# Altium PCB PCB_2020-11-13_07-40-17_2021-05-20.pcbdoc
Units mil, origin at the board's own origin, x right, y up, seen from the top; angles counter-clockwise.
Board outline 3315 x 2420 mil, 2 copper layers (Top Layer, Bottom Layer); 15 components, 15 nets, 52 pads, 0 vias.
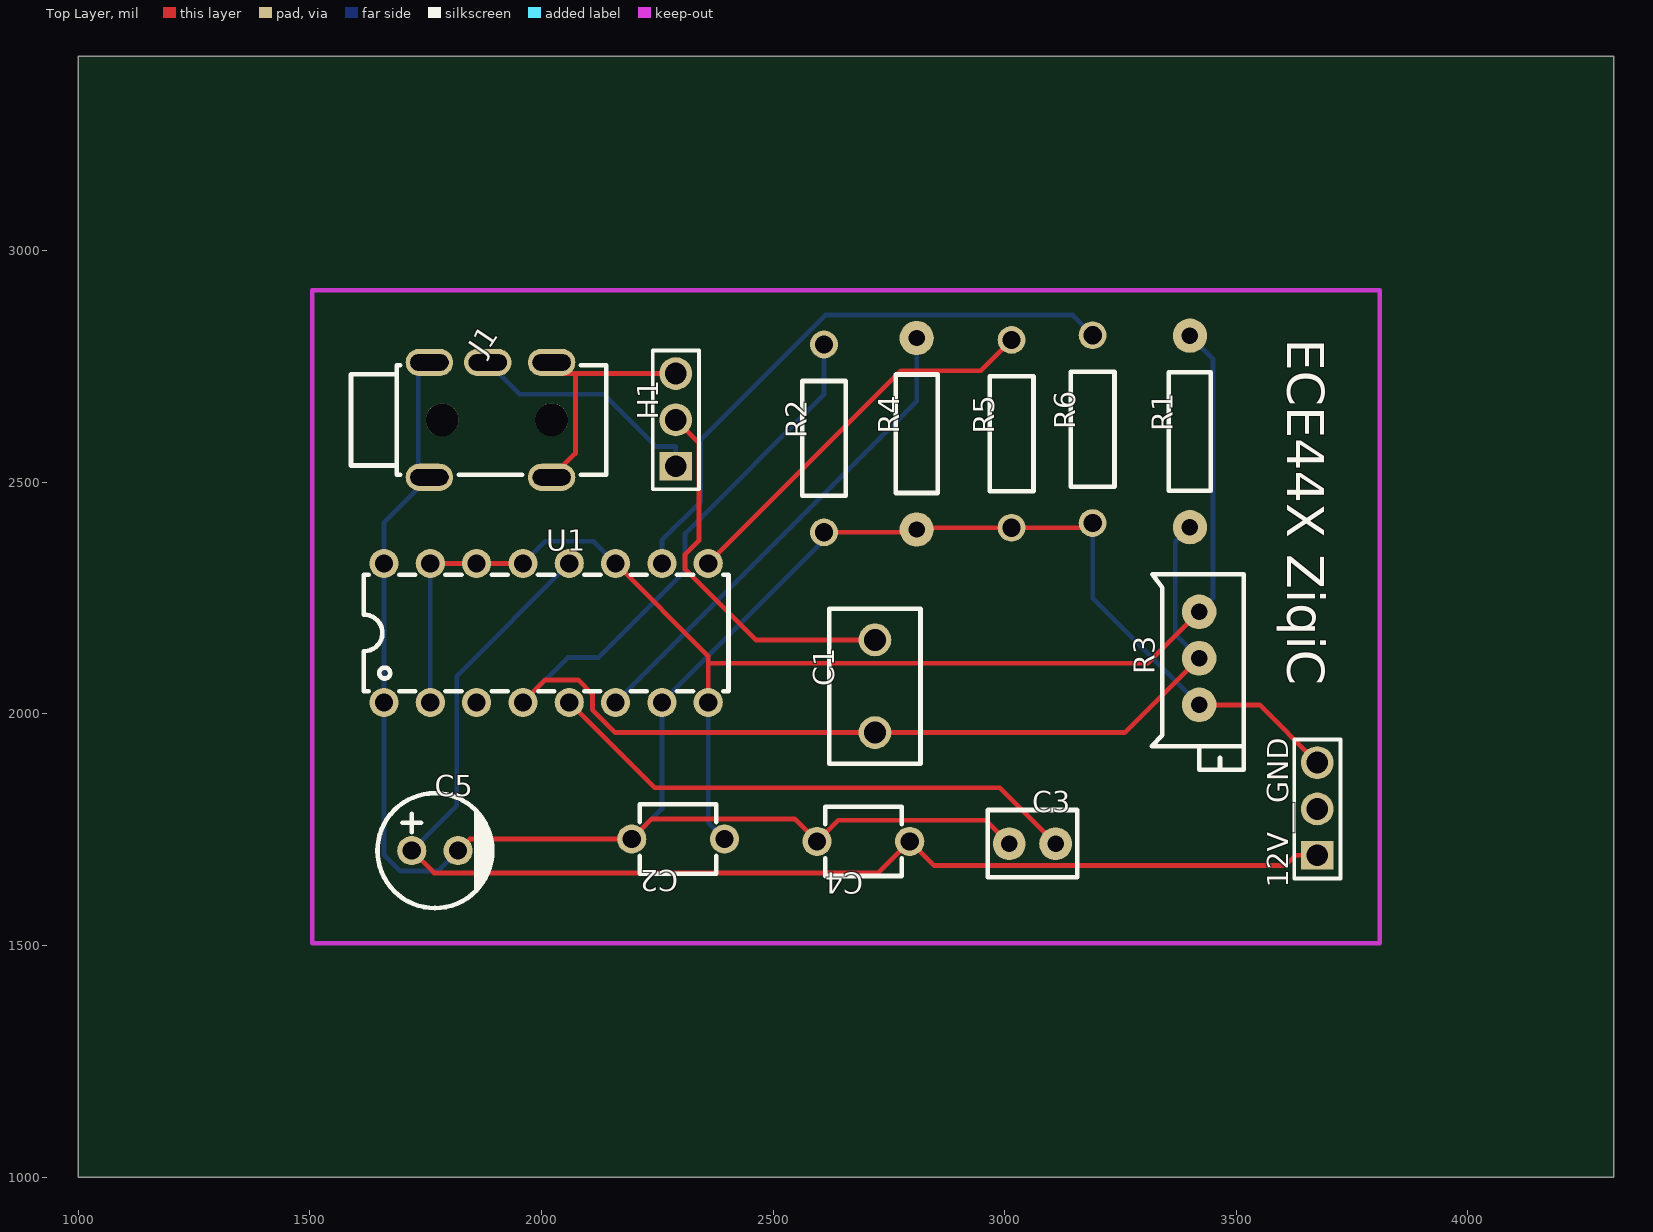
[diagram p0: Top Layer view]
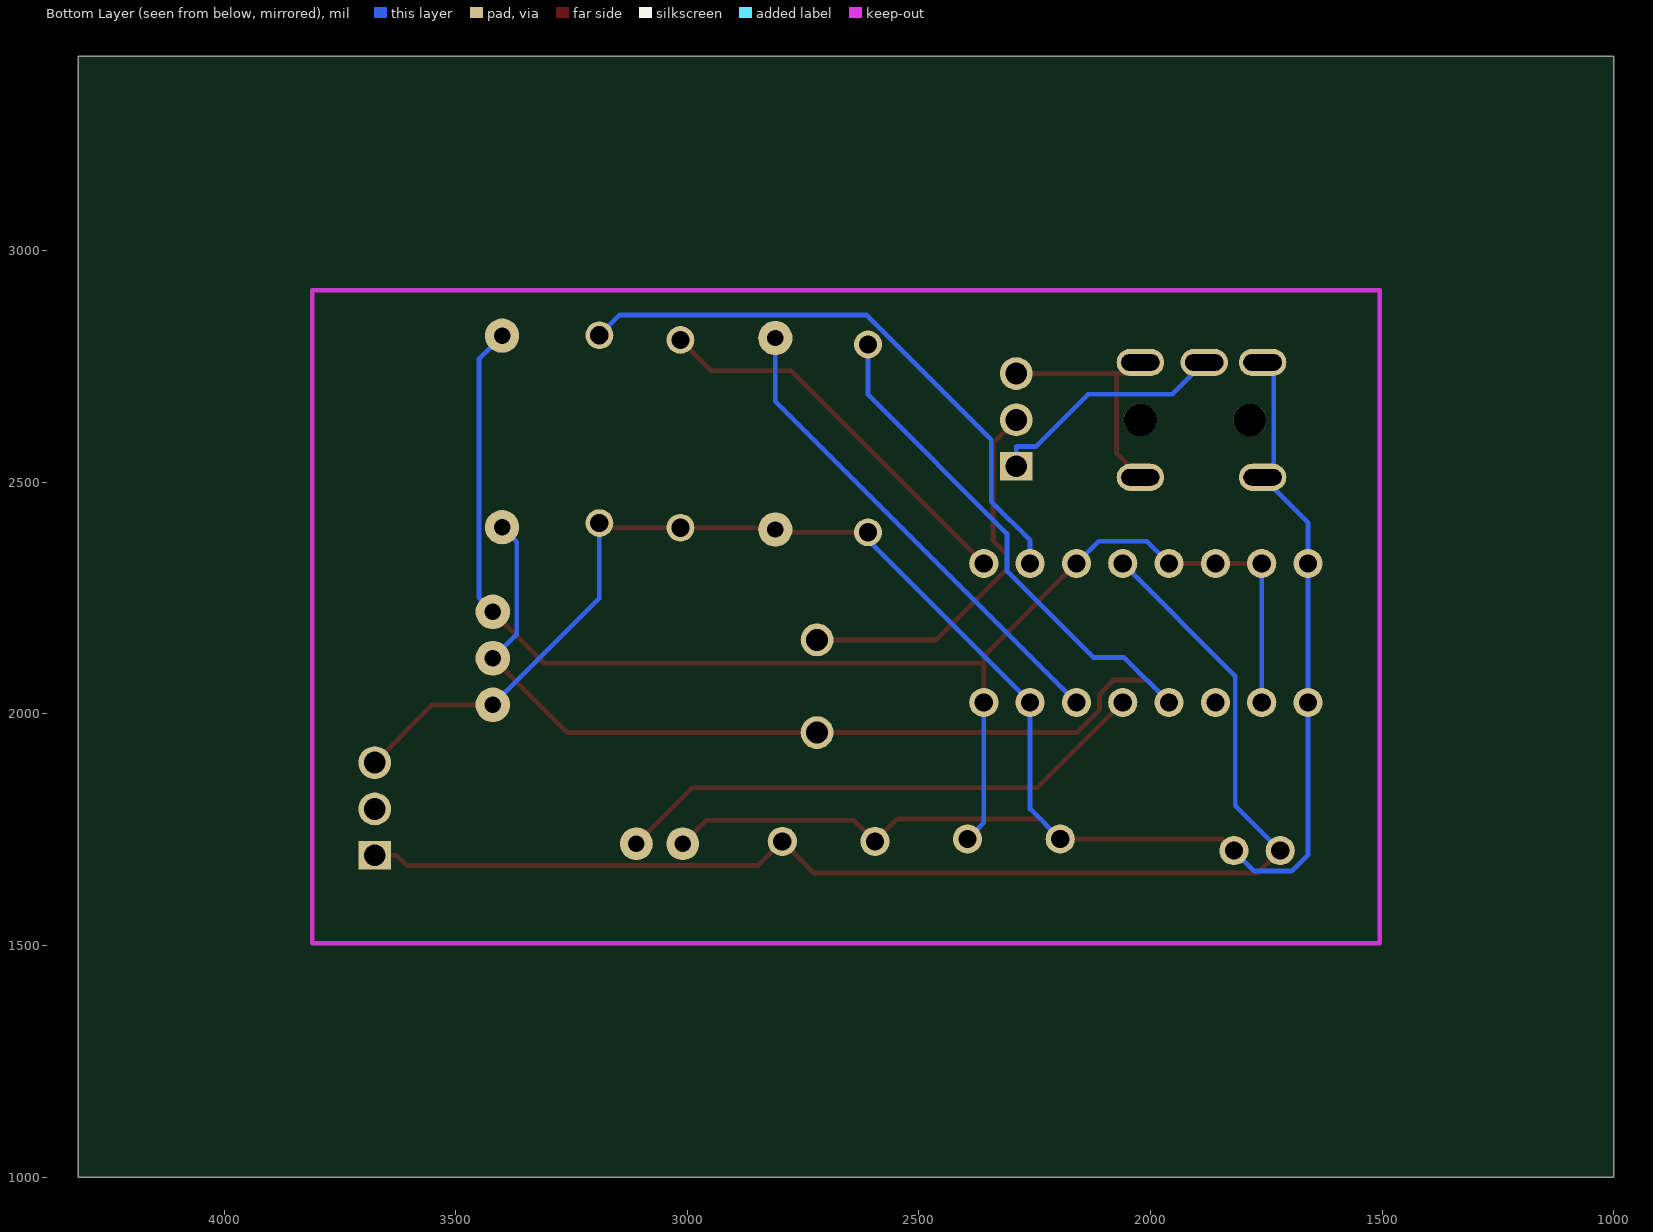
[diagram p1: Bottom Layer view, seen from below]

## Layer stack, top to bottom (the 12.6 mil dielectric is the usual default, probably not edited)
Top Layer: signal copper (thickness not stored)
Dielectric: dielectric 12.6, FR-4, Dk 4.8
Bottom Layer: signal copper (thickness not stored)

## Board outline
4315,1000 1000,1000 1000,3420 4315,3420

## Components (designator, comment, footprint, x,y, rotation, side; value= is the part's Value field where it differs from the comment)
12V__GND "12251103CNG0S115001" HDR-TH_3P-P2.54-V 3675,1795 r90 top
C1 "1uF" CAP-TH_L8.5-W5.0-P5.00-D1.2 2720,2060 r90 top
C2 "100nF" CAP-TH_L4.2-W3.8-P5.08-D0.5 2295,1730 r180 top
C3 "2.2nF" CAP-TH_L4.9-W3.7-P2.54-D0.5 3060,1720 r0 top
C4 "100nF" CAP-TH_L4.2-W3.8-P5.08-D0.5 2695,1725 r180 top
C5 "100uF" CAP-TH_BD6.3-P2.50-D1.0-FD 1770,1705 r0 top
H1 "12251103CNG0S115001" HDR-TH_3P-P2.54-V 2290,2635 r90 top
J1 "PJ313D" AUDIO-TH_PJ313D 1890,2635 r0 top
R1 "7.5K" RES-TH_BD2.3-L6.5-P10.50-D0.5 3400,2610 r90 top
R2 "2.7K" RES-TH_BD2.4-L6.3-P10.30-D0.6 2610,2595 r90 top
R3 "50K" RES-ADJ-TH_3P-L9.5-W4.9-P2.50-L_3296X 3420,2120 r90 top
R4 "7.5K" RES-TH_BD2.3-L6.5-P10.50-D0.5 2810,2605 r90 top
R5 "10K" RES-TH_BD2.4-L6.3-P10.30-D0.6 3015,2605 r90 top
R6 "10K" RES-TH_BD2.4-L6.3-P10.30-D0.6 3190,2615 r90 top
U1 "TL494N" DIP-16_L20.0-W6.4-P2.54-LS7.6-BL 2010,2175 r0 top

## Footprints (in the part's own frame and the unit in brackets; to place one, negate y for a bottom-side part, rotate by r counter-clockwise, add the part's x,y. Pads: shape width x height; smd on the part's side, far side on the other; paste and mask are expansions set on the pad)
AUDIO-TH_PJ313D [mm]
  oval 2.6x1.5 hole 0.9 slot 2.1 at 0 deg: 2(-3.35,-3.15) 2(-3.35,3.15) 3(-0.15,3.15) 4(3.35,-3.15) 4(3.35,3.15)
  round 1.8 hole 1.8 unplated: ""(-2.65,0) ""(3.35,0)
  silkscreen extent -7.65,-3 6.35,3
CAP-TH_BD6.3-P2.50-D1.0-FD [mm]
  round 1.6 hole 1: 1(-1.27,0) 2(1.27,0)
  silkscreen extent -3.15,-3.15 3.17,3.15
CAP-TH_L4.2-W3.8-P5.08-D0.5 [mm]
  round 1.6 hole 1: 1(-2.54,0) 2(2.54,0)
  silkscreen extent -2.1,-1.9 2.1,1.9
CAP-TH_L4.9-W3.7-P2.54-D0.5 [mm]
  round 1.8 hole 0.9: 1(-1.27,0) 2(1.27,0)
  silkscreen extent -2.45,-1.85 2.45,1.85
CAP-TH_L8.5-W5.0-P5.00-D1.2 [mm]
  round 1.8 hole 1.2: 1(-2.54,0) 2(2.54,0)
  silkscreen extent -4.25,-2.5 4.25,2.5
DIP-16_L20.0-W6.4-P2.54-LS7.6-BL [mm]
  round 1.6 hole 1: 1(-8.89,-3.81) 2(-6.35,-3.81) 3(-3.81,-3.81) 4(-1.27,-3.81) 5(1.27,-3.81) 6(3.81,-3.81) 7(6.35,-3.81) 8(8.89,-3.81) 9(8.89,3.81) 10(6.35,3.81) 11(3.81,3.81) 12(1.27,3.81) 13(-1.27,3.81) 14(-3.81,3.81) 15(-6.35,3.81) 16(-8.89,3.81)
  silkscreen extent -10,-3.2 10,3.2
HDR-TH_3P-P2.54-V [mm]
  rect 1.575x1.8 hole 1.2: 1(-2.54,0)
  round 1.8 hole 1.2: 2(0,0) 3(2.54,0)
  silkscreen extent -3.81,-1.27 3.81,1.27
RES-ADJ-TH_3P-L9.5-W4.9-P2.50-L_3296X [mm]
  round 1.9 hole 0.9: 1(2.55,0) 2(0.01,0) 3(-2.55,0)
  silkscreen extent -6.1,-2.45 4.61,2.6
RES-TH_BD2.3-L6.5-P10.50-D0.5 [mil]
  round 74 hole 35.4: 1(-206.69,0) 2(206.69,0)
  silkscreen extent -128,-45 128,45
RES-TH_BD2.4-L6.3-P10.30-D0.6 [mil]
  round 60 hole 39.37: 1(-202.76,0) 2(202.76,0)
  silkscreen extent -124,-47 124,47

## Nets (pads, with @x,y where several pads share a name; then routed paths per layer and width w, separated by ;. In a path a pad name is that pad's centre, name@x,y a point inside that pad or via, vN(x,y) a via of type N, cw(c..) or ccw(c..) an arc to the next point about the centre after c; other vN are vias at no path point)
12V: 12V__GND.1 C4.1 C5.1 U1.12 | length 2794.7
  Top Layer w10.24: C5.1 1768.2,1656.8 2726.8,1656.8 C4.1 2847,1673 3606,1673 3628.1,1695 12V__GND.1
  Bottom Layer w10.24: C5.1 1817,1802 1817,2082 U1.12
GND: 12V__GND.3 C2.2 C3.1 C4.2 C5.2 J1.2 R2.1 R3.3 R4.1 R5.1 R6.1 U1.1 U1.7 U1.16 | length 6032.6
  Top Layer w10.24: C5.2 1845,1730 C2.2 2238.3,1773.3 2546.7,1773.3 C4.2 2640.6,1770.6 2959.4,1770.6 C3.1 ; R2.1 2803.9,2392.2 R4.1 ; R6.1 3180,2402.2 R5.1 ; R3.3 3550.4,2019.6 12V__GND.3 ; R4.1 R4.1@2813.9,2402.2 ; R4.1 R4.1@2813.9,2402.2 ; R4.1@2813.9,2402.2 R5.1 ; R4.1@2813.9,2402.2 R5.1
  Bottom Layer w10.24: J1.2@1758.1,2759 1733.7,2734.6 1733.7,2535.4 J1.2@1758.1,2511 ; C5.2 1775.9,1660.9 1695.4,1660.9 1660,1696.3 U1.1 ; C2.2 2260,1795 U1.7 2610,2375 R2.1 ; U1.1 U1.16 ; U1.1 U1.16 ; U1.16 1660,2412.9 ; U1.16 1660,2412.9 ; 1660,2412.9 J1.2@1758.1,2511 ; 1660,2412.9 J1.2@1758.1,2511 ; 3190,2249.6 R3.3 3190,2249.6 ; 3190,2249.6 R6.1 3190,2249.6
H1_2: C1.2 H1.2 | length 828.5
  Top Layer w10.24: H1.2 2339.9,2585.1 2339.9,2374.2 2310,2344.4 2310,2312.9 2462.9,2160 C1.2
H2_2: 12V__GND.2
J1_3: H1.1 J1.3 | length 523.6
  Bottom Layer w10.24: J1.3 1952.8,2690.3 2134.7,2690.3 2247.5,2577.5 2290,2577.5 H1.1
J1_4: H1.3 J1.4 | length 523.4
  Top Layer w10.24: J1.4@2021.9,2511 2073.4,2562.5 2073.4,2735 ; J1.4@2021.9,2759 2045.9,2735 2073.4,2735 ; H1.3 2073.4,2735
S$6: 
S$8: 
SIGNALA: R5.2 U1.9 | length 855
  Top Layer w10.24: U1.9 2776.2,2741.2 2948.5,2741.2 R5.2
SIGNALB: R6.2 U1.10 | length 1277.3
  Bottom Layer w10.24: U1.10 2260,2374.9 2343.8,2458.7 2343.8,2591.8 2613.2,2861.2 3146.6,2861.2 R6.2
U1_2: C2.1 R1.2 R3.1 U1.2 U1.8 U1.11 U1.13 U1.14 U1.15 | length 3167.5
  Top Layer w10.24: U1.15 U1.14 U1.13 ; U1.11 2360,2125 2360,2109.4 ; U1.8 2360,2109.4 ; R3.1 3309,2109.4 2360,2109.4
  Bottom Layer w10.24: U1.2 U1.15 ; U1.13 2008.2,2373.2 2111.8,2373.2 U1.11 ; U1.8 2360,1765 C2.1 ; R1.2 3449.8,2766.9 3449.8,2250.2 R3.1
U1_3: U1.3
U1_4: C1.1 R1.1 R2.2 R3.2 U1.4 | length 3010.8
  Top Layer w10.24: U1.4 2008.5,2073.5 2079.1,2073.5 2110,2042.6 2110,2009.6 2159.6,1960 C1.1 3259.6,1960 R3.2
  Bottom Layer w10.24: U1.4 2056.9,2121.9 2123,2121.9 2310,2308.9 2310,2389.6 2610,2689.6 R2.2 ; R1.1 3368.6,2371.9 3368.6,2171.8 R3.2
U1_5: C3.2 U1.5 | length 1176.3
  Top Layer w10.24: U1.5 2244.4,1840.6 2989.4,1840.6 C3.2
U1_6: R4.2 U1.6 | length 1055.9
  Bottom Layer w10.24: U1.6 2810,2675 R4.2
pads on no net: J1.

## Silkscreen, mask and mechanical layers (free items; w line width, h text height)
Top Overlay:
  text "ECE44X ZiqiC" at 3610,2810 h80 r270
Document:
  lines w0.1: 2656.5,2209 2658.5,2211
